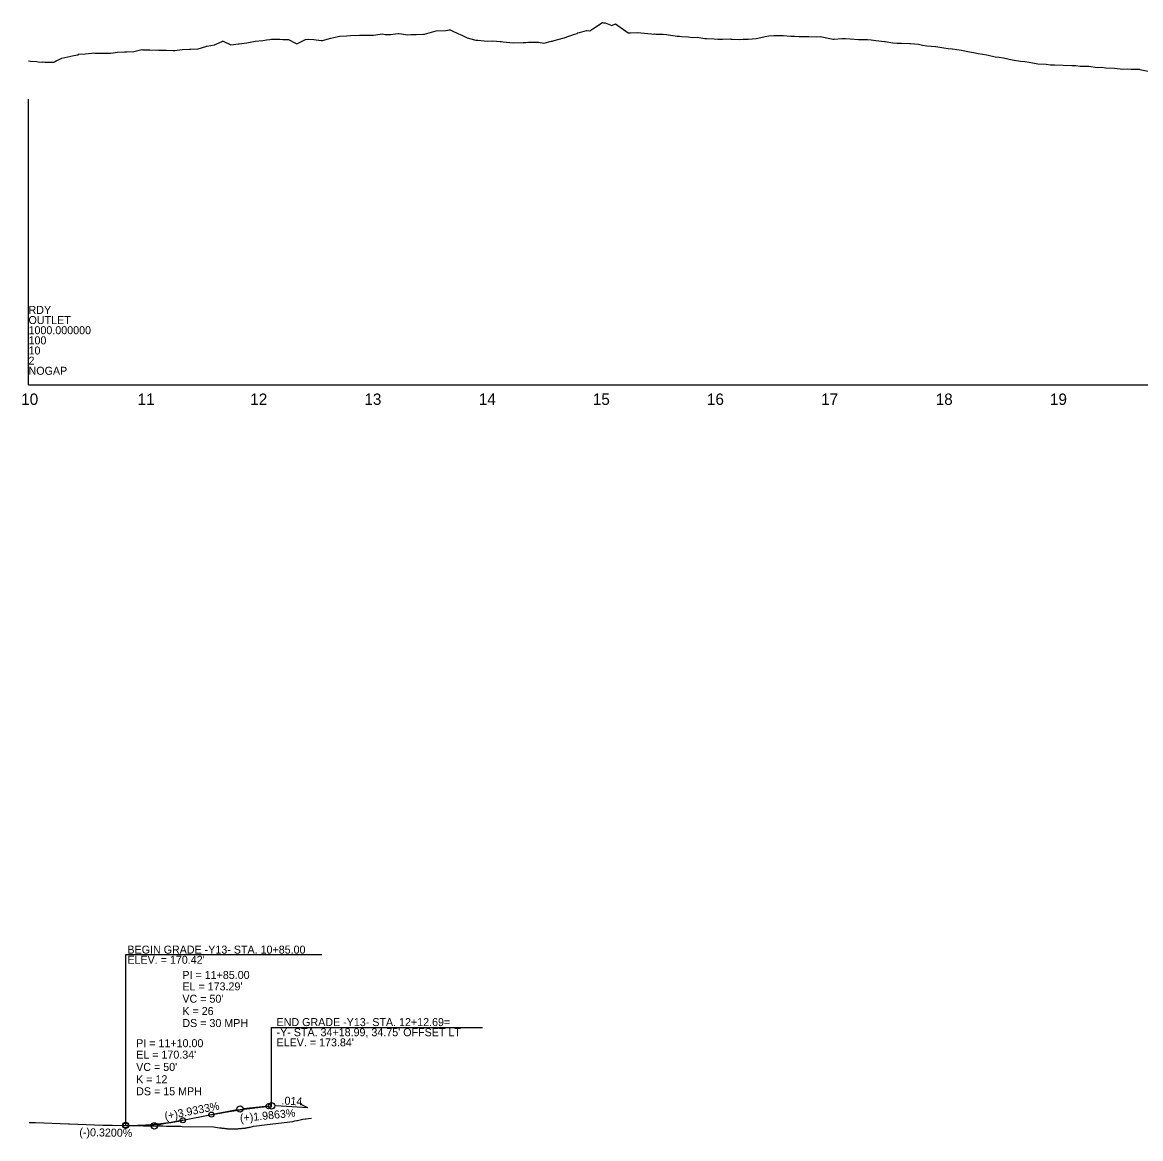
# Model space of a CAD drawing. Extents: x 1778432 to 1784301, y 601022 to 621789.
# Drawn here: x 1780138 to 1781116, y 602380 to 603356 of the extents above; entities that cross this region are included whole.
import ezdxf

# ---------------------------------------------------------------- set-up
doc = ezdxf.new("R2010")
doc.units = 0
for name, color, linetype in [('Exist Profile Cell', 7, 'Continuous'), ('Exist Vertical Profile Ground Line', 7, 'Continuous'), ('Exist Vertical Profile Horizontal Axis Label Major', 7, 'Continuous'), ('Prop Vertical Profile Curve Label', 7, 'Continuous'), ('Prop Vertical Profile Grade', 7, 'Continuous'), ('Prop Vertical Profile Grade Label', 7, 'Continuous'), ('Prop VPI Label', 7, 'Continuous')]:
    doc.layers.add(name, color=color, linetype=linetype)

msp = doc.modelspace()

# ---------------------------------------------------------------- linework, layer by layer
at = {"layer": 'Exist Profile Cell'}
for q in [(1780142.96, 603289.19), (1782139.87, 603039.19), (1780142.96, 603039.19)]:
    msp.add_line((1780142.96, 603039.19), q, dxfattribs=at)
at = {"layer": 'Exist Vertical Profile Ground Line'}
for points in [[(1780142.96, 603322.67), (1780144.73, 603322.51), (1780150.08, 603322.23), (1780151.46, 603322.01), (1780155.13, 603321.52), (1780155.69, 603321.87), (1780157.15, 603321.71), (1780158.76, 603321.71), (1780164.25, 603321.58), (1780165.07, 603321.59), (1780165.58, 603321.93), (1780166.99, 603322.88), (1780170.26, 603324.35), (1780172.06, 603324.96), (1780182.67, 603327.47), (1780184.33, 603327.81), (1780185.45, 603327.91), (1780186.48, 603328.11), (1780186.83, 603328.71), (1780192.51, 603328.92), (1780198.27, 603329.56), (1780199.58, 603329.62), (1780200.86, 603329.52), (1780212.52, 603329.36), (1780213.72, 603329.51), (1780214.9, 603329.48), (1780220.79, 603330.24), (1780226.78, 603330.53), (1780228.93, 603330.69), (1780234.93, 603330.82), (1780241.03, 603332.35), (1780242, 603332.59), (1780242.97, 603332.46), (1780249.08, 603332.45), (1780255.28, 603332.08), (1780256.15, 603332.23), (1780257, 603332.14), (1780263.22, 603332.02), (1780269.53, 603331.75), (1780270.29, 603331.87), (1780271.04, 603331.85), (1780277.36, 603332.8), (1780283.78, 603333.03), (1780284.43, 603333.1), (1780285.07, 603333.04), (1780291.5, 603333.16), (1780298.04, 603335.23), (1780298.57, 603335.44), (1780299.1, 603335.47), (1780305.65, 603336.75), (1780312.29, 603339.77), (1780312.72, 603339.91), (1780313.14, 603339.86), (1780319.79, 603336.83), (1780326.54, 603337.51), (1780326.86, 603337.48), (1780327.17, 603337.54), (1780333.93, 603338.36), (1780341.21, 603339.9), (1780348.07, 603340.6), (1780351, 603341.07), (1780354.18, 603341.48), (1780355.37, 603341.6), (1780357.73, 603341.59), (1780362.81, 603341.76), (1780365.37, 603341.55), (1780370.26, 603341.44), (1780376.56, 603338.11), (1780377.71, 603337.6), (1780380, 603338.72), (1780385.16, 603341.34), (1780387.75, 603341.8), (1780392.61, 603341.53), (1780398.94, 603340.6), (1780400.06, 603340.63), (1780402.27, 603341.09), (1780407.51, 603342.46), (1780410.14, 603343.08), (1780414.95, 603344.3), (1780421.33, 603344.55), (1780424.55, 603344.78), (1780432.52, 603345.12), (1780437.3, 603345.3), (1780443.71, 603345.08), (1780444.75, 603345.08), (1780446.82, 603345.36), (1780452.2, 603346.25), (1780454.9, 603345.89), (1780459.65, 603345.82), (1780466.09, 603346.76), (1780467.1, 603346.71), (1780469.09, 603346.48), (1780474.54, 603345.56), (1780477.28, 603345.71), (1780481.99, 603345.76), (1780488.48, 603346.06), (1780489.44, 603346.03), (1780491.36, 603346.74), (1780499.67, 603348.96), (1780508.05, 603349.37), (1780510.86, 603349.97), (1780511.79, 603349.87), (1780513.63, 603349.07), (1780519.24, 603346.23), (1780522.05, 603345.15), (1780526.68, 603342.76), (1780533.24, 603341.25), (1780534.13, 603340.92), (1780535.91, 603340.71), (1780541.58, 603340.26), (1780544.43, 603340.09), (1780549.03, 603340.3), (1780555.62, 603339.71), (1780556.48, 603339.56), (1780558.18, 603339.42), (1780566.82, 603338.64), (1780575.54, 603338.85), (1780578.01, 603338.93), (1780580.45, 603338.94), (1780589.2, 603339.05), (1780593.72, 603338.07), (1780600.39, 603339.84), (1780601.17, 603340.05), (1780602.72, 603340.54), (1780611.58, 603343), (1780620.53, 603346.04), (1780622.77, 603346.8), (1780623.52, 603347.15), (1780625, 603347.48), (1780630.97, 603349.37), (1780633.97, 603348.88), (1780638.41, 603351.88), (1780645.16, 603356.41), (1780645.86, 603356.02), (1780647.27, 603355.96), (1780653.31, 603353.79), (1780656.35, 603355.17), (1780665.52, 603348.68), (1780667.54, 603347.22), (1780668.21, 603347.14), (1780669.54, 603347.19), (1780675.66, 603347.66), (1780678.73, 603347.24), (1780688.01, 603346.27), (1780689.92, 603346.16), (1780690.55, 603346.24), (1780691.81, 603346.16), (1780698, 603345.97), (1780701.11, 603345.86), (1780710.51, 603344.44), (1780712.31, 603344.35), (1780714.08, 603344.06), (1780720.35, 603343.68), (1780723.5, 603343.27), (1780727.8, 603343.37), (1780734.69, 603342.23), (1780735.25, 603342.27), (1780736.36, 603342.15), (1780742.7, 603342.06), (1780745.88, 603341.7), (1780750.14, 603341.83), (1780757.07, 603341.9), (1780757.59, 603341.84), (1780758.63, 603341.79), (1780765.04, 603341.48), (1780768.26, 603341.67), (1780772.49, 603341.7), (1780779.45, 603342.29), (1780780.9, 603342.56), (1780787.39, 603343.92), (1780790.65, 603344.49), (1780794.84, 603345.02), (1780801.84, 603344.96), (1780802.28, 603344.96), (1780803.17, 603344.91), (1780809.73, 603344.39), (1780813.03, 603344.41), (1780817.18, 603344.14), (1780824.22, 603343.93), (1780824.63, 603343.92), (1780825.45, 603343.93), (1780832.08, 603343.78), (1780835.41, 603344.09), (1780845.48, 603342.02), (1780846.6, 603341.85), (1780846.98, 603341.85), (1780847.72, 603341.83), (1780854.42, 603342.32), (1780857.79, 603342.21), (1780861.87, 603342.13), (1780868.99, 603341.31), (1780869.32, 603341.33), (1780869.99, 603341.32), (1780876.77, 603341.51), (1780880.18, 603341.04), (1780884.22, 603340.45), (1780891.67, 603339.73), (1780892.26, 603339.61), (1780899.12, 603338.42), (1780902.56, 603338.14), (1780906.57, 603338.21), (1780914.01, 603337.96), (1780914.53, 603337.92), (1780921.46, 603337.26), (1780924.94, 603336.56), (1780928.91, 603335.87), (1780936.36, 603335.24), (1780936.81, 603335.15), (1780943.81, 603333.98), (1780947.33, 603333.66), (1780950.89, 603333.37), (1780951.26, 603333.34), (1780958.7, 603332.1), (1780959.07, 603332.04), (1780966.15, 603330.72), (1780969.72, 603329.9), (1780973.6, 603329.2), (1780981.3, 603327.95), (1780988.49, 603326.27), (1780992.11, 603325.99), (1780995.94, 603325.4), (1781003.54, 603323.73), (1781010.83, 603322.36), (1781014.5, 603322.02), (1781018.28, 603321.7), (1781025.78, 603320.18), (1781033.17, 603319.83), (1781036.89, 603319.32), (1781040.62, 603319.2), (1781048.09, 603318.97), (1781055.51, 603318.62), (1781059.28, 603318.63), (1781062.96, 603318.02), (1781070.48, 603317.95), (1781077.85, 603317.04), (1781081.68, 603317.07), (1781085.3, 603316.71), (1781092.87, 603316.24), (1781100.19, 603315.57), (1781104.07, 603315.61), (1781107.64, 603315.37), (1781114.73, 603315.33), (1781115.26, 603315.27), (1781122.53, 603313.67)], [(1780143.48, 602393.96), (1780147.94, 602393.79), (1780148.92, 602393.76), (1780177.94, 602392.69), (1780178.65, 602392.67), (1780207.94, 602391.59), (1780216.39, 602391.46), (1780243.56, 602391.04), (1780244.97, 602391.02), (1780246.24, 602391), (1780246.93, 602390.99), (1780250.29, 602390.94), (1780253.66, 602390.88), (1780256.1, 602390.85), (1780257.02, 602390.83), (1780260.39, 602390.78), (1780263.75, 602390.72), (1780267.12, 602390.66), (1780270.49, 602390.6), (1780273.85, 602390.54), (1780275.95, 602390.5), (1780276.32, 602390.49), (1780277.22, 602390.47), (1780304.73, 602389.94), (1780306.55, 602389.88), (1780309.93, 602389.19), (1780310.93, 602389.09), (1780311.48, 602389.03), (1780312.02, 602388.98), (1780312.56, 602388.92), (1780313.1, 602388.86), (1780313.64, 602388.8), (1780314.18, 602388.74), (1780314.72, 602388.67), (1780315.26, 602388.61), (1780315.8, 602388.54), (1780316.35, 602388.48), (1780316.89, 602388.41), (1780317.57, 602388.33), (1780317.97, 602388.34), (1780318.51, 602388.34), (1780319.05, 602388.34), (1780319.59, 602388.34), (1780320.13, 602388.34), (1780320.6, 602388.34), (1780321.22, 602388.33), (1780321.76, 602388.33), (1780322.3, 602388.32), (1780322.97, 602388.32), (1780323.38, 602388.32), (1780323.92, 602388.31), (1780324.46, 602388.3), (1780325.14, 602388.28), (1780325.54, 602388.33), (1780326.09, 602388.39), (1780326.63, 602388.45), (1780327.17, 602388.51), (1780327.71, 602388.57), (1780328.25, 602388.62), (1780328.79, 602388.68), (1780329.33, 602388.73), (1780329.87, 602388.79), (1780330.41, 602388.84), (1780330.96, 602388.88), (1780331.5, 602388.93), (1780332.04, 602388.98), (1780332.74, 602389.02), (1780333.12, 602389.11), (1780333.66, 602389.23), (1780334.2, 602389.34), (1780334.74, 602389.46), (1780335.28, 602389.57), (1780335.83, 602389.68), (1780336.37, 602389.79), (1780336.91, 602389.9), (1780339.9, 602390.49), (1780345, 602391.08), (1780346.72, 602391.5), (1780374.28, 602394.74), (1780375.94, 602395.16), (1780377.4, 602395.53), (1780377.8, 602395.63), (1780378.16, 602395.7), (1780380.56, 602396.16), (1780382.95, 602396.63), (1780385.34, 602396.94), (1780385.82, 602397), (1780387.81, 602397.27), (1780390.46, 602397.71)]]:
    msp.add_lwpolyline(points, dxfattribs=at)
at = {"layer": 'Prop Vertical Profile Curve Label'}
for centre in [(1780302.96, 602400.73), (1780352.96, 602408.12), (1780227.96, 602391.29), (1780277.96, 602395.81)]:
    msp.add_circle(centre, 2.25, dxfattribs=at)
at = {"layer": 'Prop Vertical Profile Grade'}
for p, q in [((1780352.96, 602408.12), (1780355.65, 602408.39)), ((1780277.96, 602395.81), (1780302.96, 602400.73))]:
    msp.add_line(p, q, dxfattribs=at)
for points in [[(1780302.96, 602400.73), (1780303.96, 602400.92), (1780304.96, 602401.11), (1780305.96, 602401.31), (1780306.96, 602401.5), (1780307.96, 602401.68), (1780308.96, 602401.87), (1780309.96, 602402.05), (1780310.96, 602402.24), (1780311.96, 602402.42), (1780312.96, 602402.59), (1780313.96, 602402.77), (1780314.96, 602402.94), (1780315.96, 602403.12), (1780316.96, 602403.29), (1780317.96, 602403.46), (1780318.96, 602403.62), (1780319.96, 602403.79), (1780320.96, 602403.95), (1780321.96, 602404.11), (1780322.96, 602404.27), (1780323.96, 602404.43), (1780324.96, 602404.58), (1780325.96, 602404.73), (1780326.96, 602404.88), (1780327.96, 602405.03), (1780328.96, 602405.18), (1780329.96, 602405.33), (1780330.96, 602405.47), (1780331.96, 602405.61), (1780332.96, 602405.75), (1780333.96, 602405.89), (1780334.96, 602406.02), (1780335.96, 602406.15), (1780336.96, 602406.29), (1780337.96, 602406.42), (1780338.96, 602406.54), (1780339.96, 602406.67), (1780340.96, 602406.79), (1780341.96, 602406.91), (1780342.96, 602407.03), (1780343.96, 602407.15), (1780344.96, 602407.27), (1780345.96, 602407.38), (1780346.96, 602407.49), (1780347.96, 602407.6), (1780348.96, 602407.71), (1780349.96, 602407.82), (1780350.96, 602407.92), (1780351.96, 602408.02), (1780352.96, 602408.12)], [(1780227.96, 602391.29), (1780228.96, 602391.28), (1780229.96, 602391.27), (1780230.96, 602391.26), (1780231.96, 602391.26), (1780232.96, 602391.26), (1780233.96, 602391.27), (1780234.96, 602391.28), (1780235.96, 602391.3), (1780236.96, 602391.32), (1780237.96, 602391.34), (1780238.96, 602391.37), (1780239.96, 602391.41), (1780240.96, 602391.44), (1780241.96, 602391.48), (1780242.96, 602391.53), (1780243.96, 602391.58), (1780244.96, 602391.63), (1780245.96, 602391.69), (1780246.96, 602391.76), (1780247.96, 602391.82), (1780248.96, 602391.89), (1780249.96, 602391.97), (1780250.96, 602392.05), (1780251.96, 602392.13), (1780252.96, 602392.22), (1780253.96, 602392.31), (1780254.96, 602392.41), (1780255.96, 602392.51), (1780256.96, 602392.62), (1780257.96, 602392.73), (1780258.96, 602392.84), (1780259.96, 602392.96), (1780260.96, 602393.08), (1780261.96, 602393.21), (1780262.96, 602393.34), (1780263.96, 602393.47), (1780264.96, 602393.61), (1780265.96, 602393.75), (1780266.96, 602393.9), (1780267.96, 602394.05), (1780268.96, 602394.21), (1780269.96, 602394.37), (1780270.96, 602394.54), (1780271.96, 602394.71), (1780272.96, 602394.88), (1780273.96, 602395.06), (1780274.96, 602395.24), (1780275.96, 602395.42), (1780276.96, 602395.61), (1780277.96, 602395.81)]]:
    msp.add_spline(points, degree=3, dxfattribs=at)
at = {"layer": 'Prop VPI Label'}
for p, q in [((1780227.96, 602540.73), (1780399.43, 602540.73)), ((1780227.96, 602391.29), (1780227.96, 602540.73)), ((1780355.65, 602477.09), (1780540.09, 602477.09)), ((1780355.65, 602408.39), (1780355.65, 602477.09)), ((1780302.96, 602400.73), (1780325.26, 602405.11)), ((1780352.96, 602408.12), (1780330.7, 602405.91)), ((1780387.33, 602406.72), (1780359.18, 602408.39)), ((1780387.33, 602406.72), (1780381.39, 602409.5)), ((1780277.96, 602395.81), (1780255.66, 602391.42)), ((1780227.96, 602391.29), (1780250.21, 602390.94))]:
    msp.add_line(p, q, dxfattribs=at)
for centre in [(1780327.96, 602405.64), (1780355.65, 602408.39), (1780227.96, 602391.29), (1780252.96, 602390.89)]:
    msp.add_circle(centre, 2.75, dxfattribs=at)

# ---------------------------------------------------------------- texts
at = {"layer": 'Exist Profile Cell'}
for s, p in [('RDY', (1780142.96, 603101.31)), ('OUTLET', (1780142.96, 603092.44)), ('1000.000000', (1780142.96, 603083.56)), ('100', (1780142.96, 603074.69)), ('10', (1780142.96, 603065.81)), ('2', (1780142.96, 603056.94)), ('NOGAP', (1780142.96, 603048.07))]:
    msp.add_text(s, height=7, dxfattribs=at).set_placement(p)
at = {"layer": 'Exist Vertical Profile Horizontal Axis Label Major'}
for s, p in [('10', (1780136.54, 603021.69)), ('11', (1780238.38, 603021.69)), ('12', (1780336.93, 603021.69)), ('13', (1780436.77, 603021.69)), ('14', (1780536.82, 603021.69)), ('15', (1780636.61, 603021.69)), ('16', (1780736.42, 603021.69)), ('17', (1780836.32, 603021.69)), ('18', (1780936.55, 603021.69)), ('19', (1781036.49, 603021.69))]:
    msp.add_text(s, height=10, dxfattribs=at).set_placement(p)
at = {"layer": 'Prop Vertical Profile Grade Label'}
for s, rotation, p in [('.014', 356.62164, (1780364.11, 602409.71)), ('(+)3.9333%', 11.12617, (1780262.67, 602395.86)), ('(+)1.9863%', 5.67167, (1780328.23, 602394.16)), ('(-)0.3200%', 359.08335, (1780187.35, 602381.94))]:
    msp.add_text(s, height=7, rotation=rotation, dxfattribs=at).set_placement(p)
at = {"layer": 'Prop VPI Label'}
for s, p in [('BEGIN GRADE -Y13- STA. 10+85.00', (1780229.44, 602541.6)), ("ELEV. = 170.42'", (1780229.44, 602532.73)), ('PI = 11+85.00', (1780277.55, 602519.43)), ("EL = 173.29'", (1780277.55, 602509.43)), ("VC = 50'", (1780277.55, 602498.65)), ('K = 26', (1780277.55, 602487.87)), ('DS = 30 MPH', (1780277.55, 602477.37)), ('END GRADE -Y13- STA. 12+12.69=', (1780359.93, 602478.19)), ("-Y- STA. 34+18.99, 34.75' OFFSET LT", (1780359.93, 602469.31)), ('PI = 11+10.00', (1780237.11, 602459.73)), ("ELEV. = 173.84'", (1780359.93, 602460.44)), ("EL = 170.34'", (1780237.11, 602449.73)), ("VC = 50'", (1780237.11, 602438.95)), ('K = 12', (1780237.11, 602428.17)), ('DS = 15 MPH', (1780237.11, 602417.67))]:
    msp.add_text(s, height=7, dxfattribs=at).set_placement(p)

doc.saveas('drawing.dxf')
